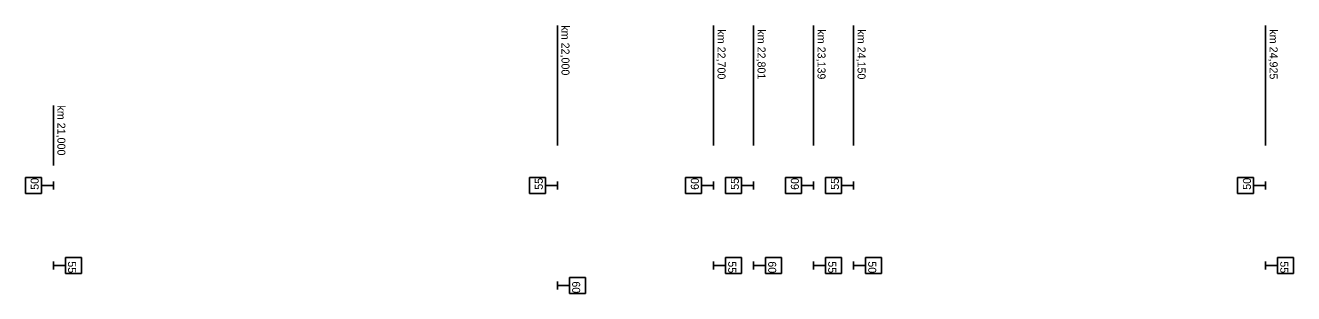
# Model space of a CAD drawing. Extents: x -591 to 5777, y 380 to 2087.
# Drawn here: x 4693 to 5010, y 1983 to 2050 of the extents above; entities that cross this region are included whole.
import ezdxf

# ---------------------------------------------------------------- set-up
doc = ezdxf.new("R2010")
doc.units = 0
doc.layers.add('rychlostník', color=7, linetype='Continuous')

msp = doc.modelspace()

# ---------------------------------------------------------------- linework, layer by layer
at = {"layer": 'rychlostník'}
for p, q in [((4826, 2020), (4826, 2050)), ((4865, 2020), (4865, 2050)), ((4865, 2020), (4865, 2050)), ((4875, 2020), (4875, 2050)), ((4875, 2020), (4875, 2050)), ((4890, 2020), (4890, 2050)), ((4890, 2020), (4890, 2050)), ((4900, 2020), (4900, 2050)), ((4900, 2020), (4900, 2050)), ((5003, 2020), (5003, 2050)), ((5003, 2020), (5003, 2050)), ((4700, 2015), (4700, 2030)), ((4693, 2008), (4693, 2012)), ((4693, 2012), (4697, 2012)), ((4697, 2012), (4697, 2008)), ((4700, 2010), (4697, 2010)), ((4700, 2009), (4700, 2011)), ((4819, 2008), (4819, 2012)), ((4819, 2012), (4823, 2012)), ((4821.33, 2010.09), (4821.33, 2010.09)), ((4823, 2012), (4823, 2008)), ((4826, 2010), (4823, 2010)), ((4826, 2009), (4826, 2011)), ((4858, 2008), (4858, 2012)), ((4858, 2012), (4862, 2012)), ((4860.33, 2010.09), (4860.33, 2010.09)), ((4862, 2012), (4862, 2008)), ((4865, 2010), (4862, 2010)), ((4865, 2009), (4865, 2011)), ((4868, 2008), (4868, 2012)), ((4868, 2012), (4872, 2012)), ((4870.33, 2010.09), (4870.33, 2010.09)), ((4872, 2012), (4872, 2008)), ((4875, 2010), (4872, 2010)), ((4875, 2009), (4875, 2011)), ((4883, 2008), (4883, 2012)), ((4883, 2012), (4887, 2012)), ((4885.33, 2010.09), (4885.33, 2010.09)), ((4887, 2012), (4887, 2008)), ((4890, 2010), (4887, 2010)), ((4890, 2009), (4890, 2011)), ((4893, 2008), (4893, 2012)), ((4893, 2012), (4897, 2012)), ((4895.33, 2010.09), (4895.33, 2010.09)), ((4897, 2012), (4897, 2008)), ((4900, 2010), (4897, 2010)), ((4900, 2009), (4900, 2011)), ((4996, 2008), (4996, 2012)), ((4996, 2012), (5000, 2012)), ((4998.33, 2010.09), (4998.33, 2010.09)), ((5000, 2012), (5000, 2008)), ((5003, 2010), (5000, 2010)), ((5003, 2009), (5003, 2011)), ((4697, 2008), (4693, 2008)), ((4823, 2008), (4819, 2008)), ((4862, 2008), (4858, 2008)), ((4872, 2008), (4868, 2008)), ((4887, 2008), (4883, 2008)), ((4897, 2008), (4893, 2008)), ((5000, 2008), (4996, 2008)), ((4700, 1991), (4700, 1989)), ((4703, 1992), (4707, 1992)), ((4703, 1988), (4703, 1992)), ((4707, 1992), (4707, 1988)), ((4865, 1991), (4865, 1989)), ((4868, 1992), (4872, 1992)), ((4868, 1988), (4868, 1992)), ((4872, 1992), (4872, 1988)), ((4875, 1991), (4875, 1989)), ((4878, 1992), (4882, 1992)), ((4878, 1988), (4878, 1992)), ((4882, 1992), (4882, 1988)), ((4890, 1991), (4890, 1989)), ((4893, 1992), (4897, 1992)), ((4893, 1988), (4893, 1992)), ((4897, 1992), (4897, 1988)), ((4900, 1991), (4900, 1989)), ((4903, 1992), (4907, 1992)), ((4903, 1988), (4903, 1992)), ((4907, 1992), (4907, 1988)), ((5003, 1991), (5003, 1989)), ((5006, 1992), (5010, 1992)), ((5006, 1988), (5006, 1992)), ((5010, 1992), (5010, 1988)), ((4700, 1990), (4703, 1990)), ((4707, 1988), (4703, 1988)), ((4865, 1990), (4868, 1990)), ((4872, 1988), (4868, 1988)), ((4869.67, 1989.91), (4869.67, 1989.91)), ((4875, 1990), (4878, 1990)), ((4882, 1988), (4878, 1988)), ((4879.67, 1989.91), (4879.67, 1989.91)), ((4890, 1990), (4893, 1990)), ((4897, 1988), (4893, 1988)), ((4894.67, 1989.91), (4894.67, 1989.91)), ((4900, 1990), (4903, 1990)), ((4907, 1988), (4903, 1988)), ((4904.67, 1989.91), (4904.67, 1989.91)), ((5003, 1990), (5006, 1990)), ((5010, 1988), (5006, 1988)), ((5007.67, 1989.91), (5007.67, 1989.91)), ((4826, 1986), (4826, 1984)), ((4826, 1985), (4829, 1985)), ((4829, 1987), (4833, 1987)), ((4829, 1983), (4829, 1987)), ((4830.67, 1984.91), (4830.67, 1984.91)), ((4833, 1987), (4833, 1983)), ((4833, 1983), (4829, 1983))]:
    msp.add_line(p, q, dxfattribs=at)

# ---------------------------------------------------------------- texts
for s, rotation, p in [('km 22,000', 270, (4827, 2050)), ('km 22,700', 270, (4866, 2049)), ('km 22,801', 270, (4876, 2049)), ('km 23,139', 270, (4891, 2049)), ('km 24,150', 270, (4901, 2049)), ('km 24,925', 270, (5004, 2049)), ('km 21,000', 270, (4701, 2030)), ('50', 90, (4696.33, 2008.93)), ('55', 90, (4822.33, 2008.93)), ('60', 90, (4861.33, 2008.93)), ('55', 90, (4871.33, 2008.93)), ('60', 90, (4886.33, 2008.93)), ('55', 90, (4896.33, 2008.93)), ('50', 90, (4999.33, 2008.93)), ('55', 270, (4703.67, 1991.07)), ('55', 270, (4868.67, 1991.07)), ('60', 270, (4878.67, 1991.07)), ('55', 270, (4893.67, 1991.07)), ('50', 270, (4903.67, 1991.07)), ('55', 270, (5006.67, 1991.07)), ('60', 270, (4829.67, 1986.07))]:
    msp.add_text(s, height=2, rotation=rotation, dxfattribs=at).set_placement(p)

doc.saveas('drawing.dxf')
